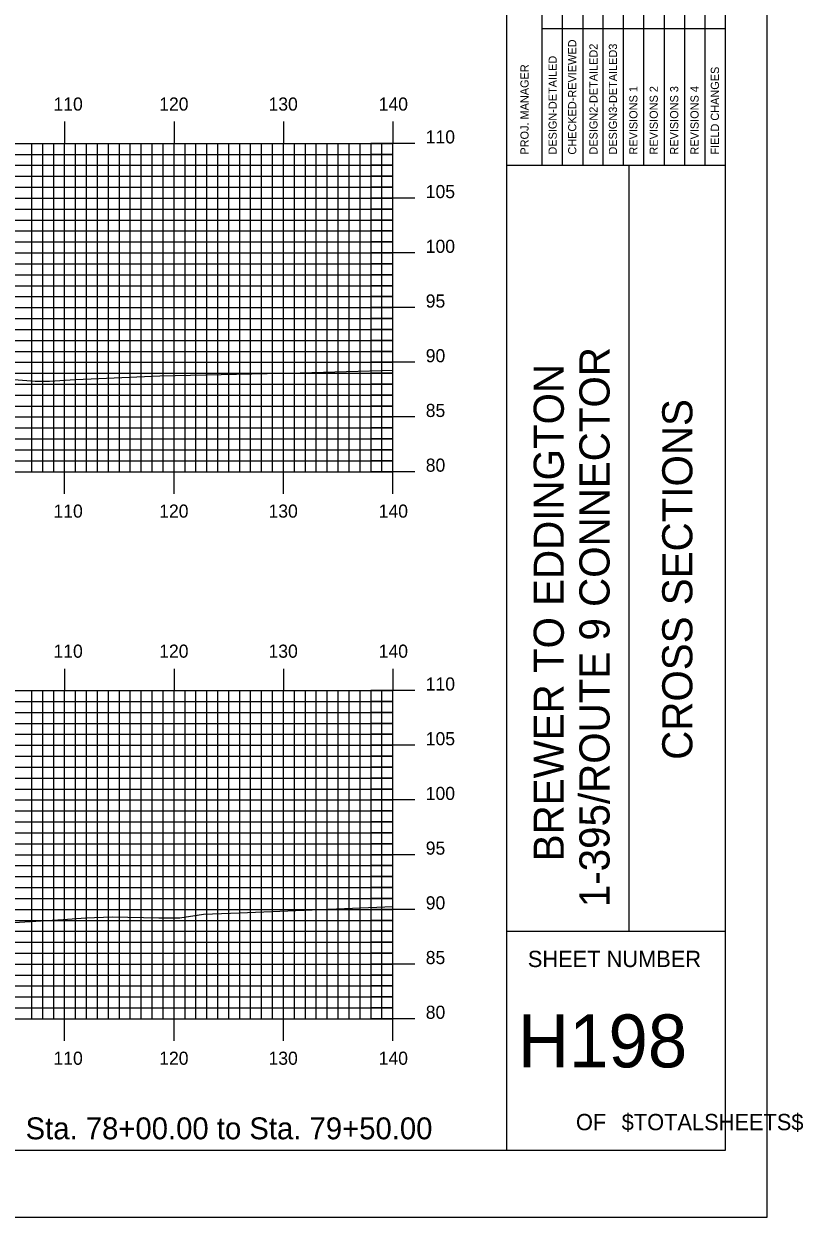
# Model space of a CAD drawing. Extents: x 1762184 to 1762528, y 442591 to 442811.
# Drawn here: x 1762456.5 to 1762527.8, y 442590.5 to 442699.6 of the extents above; entities that cross this region are included whole.
import ezdxf

# ---------------------------------------------------------------- set-up
doc = ezdxf.new("R2010")
doc.units = 0
for name, color, linetype in [('BORDER', 7, 'Continuous'), ('H_V ANNOTATION', 7, 'Continuous'), ('MAJOR', 7, 'Continuous'), ('MINOR', 7, 'Continuous'), ('PLOT BOUNDARY', 7, 'Continuous'), ('S_Roadway_Centerline', 7, 'Continuous')]:
    doc.layers.add(name, color=color, linetype=linetype)

msp = doc.modelspace()

# ---------------------------------------------------------------- linework, layer by layer
at = {"layer": 'BORDER'}
for p, q in [((1762500.67, 442596.67), (1762500.67, 442806.67)), ((1762500.67, 442686.67), (1762520.67, 442686.67)), ((1762511.85, 442616.67), (1762511.85, 442686.67)), ((1762500.67, 442616.67), (1762520.67, 442616.67))]:
    msp.add_line(p, q, dxfattribs=at)
msp.add_lwpolyline([(1762200.67, 442596.67), (1762520.67, 442596.67), (1762520.67, 442806.67), (1762200.67, 442806.67)], close=True, dxfattribs=at)
for points in [[(1762505.76, 442686.68), (1762505.76, 442721.67)], [(1762507.62, 442721.67), (1762507.62, 442686.68)], [(1762509.49, 442686.68), (1762509.49, 442721.67)], [(1762511.35, 442686.68), (1762511.35, 442721.67)], [(1762513.21, 442686.68), (1762513.21, 442721.67)], [(1762515.08, 442686.68), (1762515.08, 442721.67)], [(1762516.94, 442686.68), (1762516.94, 442721.67)], [(1762518.8, 442686.68), (1762518.8, 442721.67)], [(1762503.9, 442686.68), (1762503.9, 442720.26)], [(1762503.9, 442699.17), (1762520.67, 442699.17)]]:
    msp.add_lwpolyline(points, dxfattribs=at)
at = {"layer": 'MAJOR'}
for p, q in [((1762460.27, 442690.67), (1762460.27, 442688.67)), ((1762470.27, 442690.67), (1762470.27, 442688.67)), ((1762480.27, 442690.67), (1762480.27, 442688.67)), ((1762490.27, 442690.67), (1762490.27, 442688.67)), ((1762210.27, 442688.67), (1762490.27, 442688.67)), ((1762210.27, 442688.67), (1762490.27, 442688.67)), ((1762460.27, 442658.67), (1762460.27, 442688.67)), ((1762470.27, 442658.67), (1762470.27, 442688.67)), ((1762480.27, 442658.67), (1762480.27, 442688.67)), ((1762492.27, 442688.67), (1762488.26, 442688.67)), ((1762490.27, 442658.67), (1762490.27, 442688.67)), ((1762490.27, 442658.67), (1762490.27, 442688.67)), ((1762210.27, 442683.67), (1762490.27, 442683.67)), ((1762492.27, 442683.67), (1762488.26, 442683.67)), ((1762210.27, 442678.67), (1762490.27, 442678.67)), ((1762492.27, 442678.67), (1762488.26, 442678.67)), ((1762210.27, 442673.67), (1762490.27, 442673.67)), ((1762492.27, 442673.67), (1762488.26, 442673.67)), ((1762210.27, 442668.67), (1762490.27, 442668.67)), ((1762492.27, 442668.67), (1762488.26, 442668.67)), ((1762210.27, 442663.67), (1762490.27, 442663.67)), ((1762492.27, 442663.67), (1762488.26, 442663.67)), ((1762210.27, 442658.67), (1762490.27, 442658.67)), ((1762210.27, 442658.67), (1762490.27, 442658.67)), ((1762460.27, 442656.66), (1762460.27, 442658.67)), ((1762470.27, 442656.66), (1762470.27, 442658.67)), ((1762480.27, 442656.66), (1762480.27, 442658.67)), ((1762492.27, 442658.67), (1762488.26, 442658.67)), ((1762490.27, 442656.66), (1762490.27, 442658.67)), ((1762460.27, 442640.67), (1762460.27, 442638.67)), ((1762470.27, 442640.67), (1762470.27, 442638.67)), ((1762480.27, 442640.67), (1762480.27, 442638.67)), ((1762490.27, 442640.67), (1762490.27, 442638.67)), ((1762210.27, 442638.67), (1762490.27, 442638.67)), ((1762210.27, 442638.67), (1762490.27, 442638.67)), ((1762460.27, 442608.67), (1762460.27, 442638.67)), ((1762470.27, 442608.67), (1762470.27, 442638.67)), ((1762480.27, 442608.67), (1762480.27, 442638.67)), ((1762492.27, 442638.67), (1762488.26, 442638.67)), ((1762490.27, 442608.67), (1762490.27, 442638.67)), ((1762490.27, 442608.67), (1762490.27, 442638.67)), ((1762210.27, 442633.67), (1762490.27, 442633.67)), ((1762492.27, 442633.67), (1762488.26, 442633.67)), ((1762210.27, 442628.67), (1762490.27, 442628.67)), ((1762492.27, 442628.67), (1762488.26, 442628.67)), ((1762210.27, 442623.67), (1762490.27, 442623.67)), ((1762492.27, 442623.67), (1762488.26, 442623.67)), ((1762210.27, 442618.67), (1762490.27, 442618.67)), ((1762492.27, 442618.67), (1762488.26, 442618.67)), ((1762210.27, 442613.67), (1762490.27, 442613.67)), ((1762492.27, 442613.67), (1762488.26, 442613.67)), ((1762210.27, 442608.67), (1762490.27, 442608.67)), ((1762210.27, 442608.67), (1762490.27, 442608.67)), ((1762460.27, 442606.66), (1762460.27, 442608.67)), ((1762470.27, 442606.66), (1762470.27, 442608.67)), ((1762480.27, 442606.66), (1762480.27, 442608.67)), ((1762492.27, 442608.67), (1762488.26, 442608.67)), ((1762490.27, 442606.66), (1762490.27, 442608.67))]:
    msp.add_line(p, q, dxfattribs=at)
at = {"layer": 'MINOR'}
for p, q in [((1762457.27, 442658.67), (1762457.27, 442688.67)), ((1762458.27, 442658.67), (1762458.27, 442688.67)), ((1762459.27, 442658.67), (1762459.27, 442688.67)), ((1762461.27, 442658.67), (1762461.27, 442688.67)), ((1762462.27, 442658.67), (1762462.27, 442688.67)), ((1762463.27, 442658.67), (1762463.27, 442688.67)), ((1762464.27, 442658.67), (1762464.27, 442688.67)), ((1762465.27, 442658.67), (1762465.27, 442688.67)), ((1762466.27, 442658.67), (1762466.27, 442688.67)), ((1762467.27, 442658.67), (1762467.27, 442688.67)), ((1762468.27, 442658.67), (1762468.27, 442688.67)), ((1762469.27, 442658.67), (1762469.27, 442688.67)), ((1762471.27, 442658.67), (1762471.27, 442688.67)), ((1762472.27, 442658.67), (1762472.27, 442688.67)), ((1762473.27, 442658.67), (1762473.27, 442688.67)), ((1762474.27, 442658.67), (1762474.27, 442688.67)), ((1762475.27, 442658.67), (1762475.27, 442688.67)), ((1762476.27, 442658.67), (1762476.27, 442688.67)), ((1762477.27, 442658.67), (1762477.27, 442688.67)), ((1762478.27, 442658.67), (1762478.27, 442688.67)), ((1762479.27, 442658.67), (1762479.27, 442688.67)), ((1762481.27, 442658.67), (1762481.27, 442688.67)), ((1762482.27, 442658.67), (1762482.27, 442688.67)), ((1762483.27, 442658.67), (1762483.27, 442688.67)), ((1762484.27, 442658.67), (1762484.27, 442688.67)), ((1762485.27, 442658.67), (1762485.27, 442688.67)), ((1762486.27, 442658.67), (1762486.27, 442688.67)), ((1762487.27, 442658.67), (1762487.27, 442688.67)), ((1762488.27, 442658.67), (1762488.27, 442688.67)), ((1762489.27, 442658.67), (1762489.27, 442688.67)), ((1762210.27, 442687.67), (1762490.27, 442687.67)), ((1762490.27, 442687.67), (1762488.26, 442687.67)), ((1762210.27, 442686.67), (1762490.27, 442686.67)), ((1762490.27, 442686.67), (1762488.26, 442686.67)), ((1762210.27, 442685.67), (1762490.27, 442685.67)), ((1762490.27, 442685.67), (1762488.26, 442685.67)), ((1762210.27, 442684.67), (1762490.27, 442684.67)), ((1762490.27, 442684.67), (1762488.26, 442684.67)), ((1762210.27, 442682.67), (1762490.27, 442682.67)), ((1762490.27, 442682.67), (1762488.26, 442682.67)), ((1762210.27, 442681.67), (1762490.27, 442681.67)), ((1762490.27, 442681.67), (1762488.26, 442681.67)), ((1762210.27, 442680.67), (1762490.27, 442680.67)), ((1762210.27, 442679.67), (1762490.27, 442679.67)), ((1762490.27, 442680.67), (1762488.26, 442680.67)), ((1762490.27, 442679.67), (1762488.26, 442679.67)), ((1762210.27, 442677.67), (1762490.27, 442677.67)), ((1762490.27, 442677.67), (1762488.26, 442677.67)), ((1762210.27, 442676.67), (1762490.27, 442676.67)), ((1762490.27, 442676.67), (1762488.26, 442676.67)), ((1762210.27, 442675.67), (1762490.27, 442675.67)), ((1762490.27, 442675.67), (1762488.26, 442675.67)), ((1762210.27, 442674.67), (1762490.27, 442674.67)), ((1762490.27, 442674.67), (1762488.26, 442674.67)), ((1762210.27, 442672.67), (1762490.27, 442672.67)), ((1762490.27, 442672.67), (1762488.26, 442672.67)), ((1762210.27, 442671.67), (1762490.27, 442671.67)), ((1762490.27, 442671.67), (1762488.26, 442671.67)), ((1762210.27, 442670.67), (1762490.27, 442670.67)), ((1762490.27, 442670.67), (1762488.26, 442670.67)), ((1762210.27, 442669.67), (1762490.27, 442669.67)), ((1762490.27, 442669.67), (1762488.26, 442669.67)), ((1762210.27, 442667.67), (1762490.27, 442667.67)), ((1762490.27, 442667.67), (1762488.26, 442667.67)), ((1762210.27, 442666.67), (1762490.27, 442666.67)), ((1762490.27, 442666.67), (1762488.26, 442666.67)), ((1762210.27, 442665.67), (1762490.27, 442665.67)), ((1762490.27, 442665.67), (1762488.26, 442665.67)), ((1762210.27, 442664.67), (1762490.27, 442664.67)), ((1762490.27, 442664.67), (1762488.26, 442664.67)), ((1762210.27, 442662.67), (1762490.27, 442662.67)), ((1762490.27, 442662.67), (1762488.26, 442662.67)), ((1762210.27, 442661.67), (1762490.27, 442661.67)), ((1762490.27, 442661.67), (1762488.26, 442661.67)), ((1762210.27, 442660.67), (1762490.27, 442660.67)), ((1762490.27, 442660.67), (1762488.26, 442660.67)), ((1762210.27, 442659.67), (1762490.27, 442659.67)), ((1762490.27, 442659.67), (1762488.26, 442659.67)), ((1762457.27, 442608.67), (1762457.27, 442638.67)), ((1762458.27, 442608.67), (1762458.27, 442638.67)), ((1762459.27, 442608.67), (1762459.27, 442638.67)), ((1762461.27, 442608.67), (1762461.27, 442638.67)), ((1762462.27, 442608.67), (1762462.27, 442638.67)), ((1762463.27, 442608.67), (1762463.27, 442638.67)), ((1762464.27, 442608.67), (1762464.27, 442638.67)), ((1762465.27, 442608.67), (1762465.27, 442638.67)), ((1762466.27, 442608.67), (1762466.27, 442638.67)), ((1762467.27, 442608.67), (1762467.27, 442638.67)), ((1762468.27, 442608.67), (1762468.27, 442638.67)), ((1762469.27, 442608.67), (1762469.27, 442638.67)), ((1762471.27, 442608.67), (1762471.27, 442638.67)), ((1762472.27, 442608.67), (1762472.27, 442638.67)), ((1762473.27, 442608.67), (1762473.27, 442638.67)), ((1762474.27, 442608.67), (1762474.27, 442638.67)), ((1762475.27, 442608.67), (1762475.27, 442638.67)), ((1762476.27, 442608.67), (1762476.27, 442638.67)), ((1762477.27, 442608.67), (1762477.27, 442638.67)), ((1762478.27, 442608.67), (1762478.27, 442638.67)), ((1762479.27, 442608.67), (1762479.27, 442638.67)), ((1762481.27, 442608.67), (1762481.27, 442638.67)), ((1762482.27, 442608.67), (1762482.27, 442638.67)), ((1762483.27, 442608.67), (1762483.27, 442638.67)), ((1762484.27, 442608.67), (1762484.27, 442638.67)), ((1762485.27, 442608.67), (1762485.27, 442638.67)), ((1762486.27, 442608.67), (1762486.27, 442638.67)), ((1762487.27, 442608.67), (1762487.27, 442638.67)), ((1762488.27, 442608.67), (1762488.27, 442638.67)), ((1762489.27, 442608.67), (1762489.27, 442638.67)), ((1762210.27, 442637.67), (1762490.27, 442637.67)), ((1762490.27, 442637.67), (1762488.26, 442637.67)), ((1762210.27, 442636.67), (1762490.27, 442636.67)), ((1762490.27, 442636.67), (1762488.26, 442636.67)), ((1762210.27, 442635.67), (1762490.27, 442635.67)), ((1762490.27, 442635.67), (1762488.26, 442635.67)), ((1762210.27, 442634.67), (1762490.27, 442634.67)), ((1762490.27, 442634.67), (1762488.26, 442634.67)), ((1762210.27, 442632.67), (1762490.27, 442632.67)), ((1762490.27, 442632.67), (1762488.26, 442632.67)), ((1762210.27, 442631.67), (1762490.27, 442631.67)), ((1762210.27, 442630.67), (1762490.27, 442630.67)), ((1762490.27, 442631.67), (1762488.26, 442631.67)), ((1762490.27, 442630.67), (1762488.26, 442630.67)), ((1762210.27, 442629.67), (1762490.27, 442629.67)), ((1762490.27, 442629.67), (1762488.26, 442629.67)), ((1762210.27, 442627.67), (1762490.27, 442627.67)), ((1762490.27, 442627.67), (1762488.26, 442627.67)), ((1762210.27, 442626.67), (1762490.27, 442626.67)), ((1762490.27, 442626.67), (1762488.26, 442626.67)), ((1762210.27, 442625.67), (1762490.27, 442625.67)), ((1762490.27, 442625.67), (1762488.26, 442625.67)), ((1762210.27, 442624.67), (1762490.27, 442624.67)), ((1762490.27, 442624.67), (1762488.26, 442624.67)), ((1762210.27, 442622.67), (1762490.27, 442622.67)), ((1762490.27, 442622.67), (1762488.26, 442622.67)), ((1762210.27, 442621.67), (1762490.27, 442621.67)), ((1762490.27, 442621.67), (1762488.26, 442621.67)), ((1762210.27, 442620.67), (1762490.27, 442620.67)), ((1762490.27, 442620.67), (1762488.26, 442620.67)), ((1762210.27, 442619.67), (1762490.27, 442619.67)), ((1762490.27, 442619.67), (1762488.26, 442619.67)), ((1762210.27, 442617.67), (1762490.27, 442617.67)), ((1762490.27, 442617.67), (1762488.26, 442617.67)), ((1762210.27, 442616.67), (1762490.27, 442616.67)), ((1762490.27, 442616.67), (1762488.26, 442616.67)), ((1762210.27, 442615.67), (1762490.27, 442615.67)), ((1762490.27, 442615.67), (1762488.26, 442615.67)), ((1762210.27, 442614.67), (1762490.27, 442614.67)), ((1762490.27, 442614.67), (1762488.26, 442614.67)), ((1762210.27, 442612.67), (1762490.27, 442612.67)), ((1762490.27, 442612.67), (1762488.26, 442612.67)), ((1762210.27, 442611.67), (1762490.27, 442611.67)), ((1762490.27, 442611.67), (1762488.26, 442611.67)), ((1762210.27, 442610.67), (1762490.27, 442610.67)), ((1762490.27, 442610.67), (1762488.26, 442610.67)), ((1762210.27, 442609.67), (1762490.27, 442609.67)), ((1762490.27, 442609.67), (1762488.26, 442609.67))]:
    msp.add_line(p, q, dxfattribs=at)
at = {"layer": 'PLOT BOUNDARY'}
msp.add_lwpolyline([(1762184.48, 442590.55), (1762524.48, 442590.55), (1762524.48, 442810.55), (1762184.48, 442810.55)], close=True, dxfattribs=at)
at = {"layer": 'S_Roadway_Centerline'}
for points in [[(1762399.87, 442665.3), (1762409.23, 442665.41), (1762420.03, 442665.84), (1762422.32, 442665.88), (1762425.29, 442666.07), (1762439.83, 442666.53), (1762445.49, 442666.45), (1762450.76, 442666.72), (1762452.11, 442666.99), (1762453.28, 442667.27), (1762457.58, 442666.94), (1762458.9, 442666.95), (1762461.27, 442667.11), (1762463.39, 442667.18), (1762468.97, 442667.44), (1762480.18, 442667.67), (1762481.78, 442667.72), (1762490.27, 442667.95)], [(1762395.63, 442614.94), (1762409.26, 442615.5), (1762415.97, 442615.69), (1762431.83, 442616.45), (1762435.55, 442616.59), (1762437.19, 442616.69), (1762448.23, 442617.07), (1762456.15, 442617.49), (1762460.13, 442617.74), (1762462.19, 442617.91), (1762464.64, 442617.98), (1762468.88, 442617.9), (1762470.81, 442617.89), (1762472.96, 442618.22), (1762476.25, 442618.35), (1762490.27, 442618.95)]]:
    msp.add_lwpolyline(points, dxfattribs=at)

# ---------------------------------------------------------------- texts
at = {"layer": 'BORDER'}
for s, height, p in [('CHECKED-REVIEWED', 0.7455, (1762507.03, 442687.65)), ('DESIGN2-DETAILED2', 0.7455, (1762508.97, 442687.65)), ('DESIGN3-DETAILED3', 0.7455, (1762510.75, 442687.65)), ('DESIGN-DETAILED', 0.7455, (1762505.24, 442687.65)), ('PROJ. MANAGER', 0.7455, (1762502.67, 442687.65)), ('FIELD CHANGES', 0.7455, (1762520.07, 442687.65)), ('REVISIONS 1', 0.7455, (1762512.62, 442687.65)), ('REVISIONS 2', 0.7455, (1762514.48, 442687.65)), ('REVISIONS 3', 0.7455, (1762516.35, 442687.65)), ('REVISIONS 4', 0.7455, (1762518.21, 442687.65)), ('1-395/ROUTE 9 CONNECTOR', 2.7557, (1762510.07, 442618.87)), ('BREWER TO EDDINGTON', 2.7557, (1762505.89, 442623.07)), ('CROSS SECTIONS', 2.7557, (1762517.64, 442632.34))]:
    msp.add_text(s, height=height, rotation=90, dxfattribs=at).set_placement(p)
for s, height, p in [('SHEET NUMBER', 1.4905, (1762502.6, 442613.4)), ('H198', 4.839, (1762501.7, 442604.23)), ('$TOTALSHEETS$', 1.4905, (1762511.18, 442598.49)), ('OF', 1.491, (1762507, 442598.49))]:
    msp.add_text(s, height=height, dxfattribs=at).set_placement(p)
at = {"layer": 'H_V ANNOTATION'}
for s, height, p in [('110', 1.2, (1762459.25, 442691.67)), ('120', 1.2, (1762468.91, 442691.67)), ('130', 1.2, (1762478.9, 442691.67)), ('140', 1.2, (1762488.97, 442691.67)), ('110', 1.2, (1762493.27, 442688.67)), ('105', 1.2, (1762493.27, 442683.67)), ('100', 1.2, (1762493.27, 442678.67)), ('95', 1.2, (1762493.27, 442673.67)), ('90', 1.2, (1762493.27, 442668.67)), ('85', 1.2, (1762493.27, 442663.67)), ('80', 1.2, (1762493.27, 442658.67)), ('110', 1.2, (1762459.25, 442654.47)), ('120', 1.2, (1762468.91, 442654.47)), ('130', 1.2, (1762478.9, 442654.47)), ('140', 1.2, (1762488.97, 442654.47)), ('110', 1.2, (1762459.25, 442641.67)), ('120', 1.2, (1762468.91, 442641.67)), ('130', 1.2, (1762478.9, 442641.67)), ('140', 1.2, (1762488.97, 442641.67)), ('110', 1.2, (1762493.27, 442638.67)), ('105', 1.2, (1762493.27, 442633.67)), ('100', 1.2, (1762493.27, 442628.67)), ('95', 1.2, (1762493.27, 442623.67)), ('90', 1.2, (1762493.27, 442618.67)), ('85', 1.2, (1762493.27, 442613.67)), ('80', 1.2, (1762493.27, 442608.67)), ('110', 1.2, (1762459.25, 442604.47)), ('120', 1.2, (1762468.91, 442604.47)), ('130', 1.2, (1762478.9, 442604.47)), ('140', 1.2, (1762488.97, 442604.47)), ('Sta. 78+00.00 to Sta. 79+50.00', 2.0004, (1762456.7, 442597.66))]:
    msp.add_text(s, height=height, dxfattribs=at).set_placement(p)

doc.saveas('drawing.dxf')
